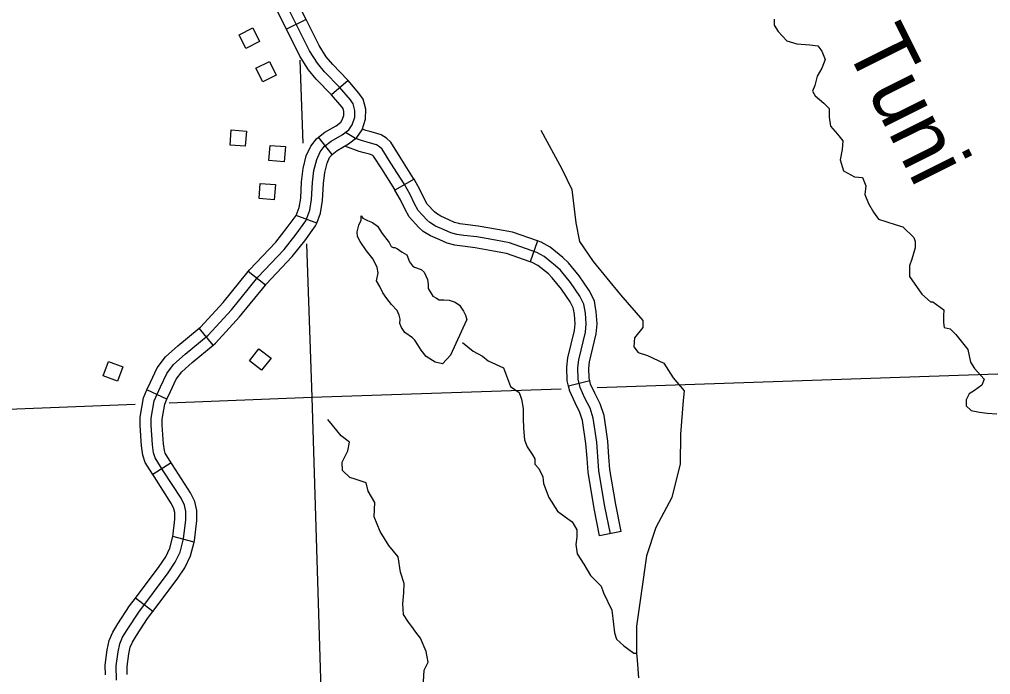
# Model space of a CAD drawing. Extents: x 155 to 3386, y 68 to 2138.
# Drawn here: x 1964.7 to 2154, y 695.1 to 823 of the extents above; entities that cross this region are included whole.
import ezdxf

# ---------------------------------------------------------------- set-up
doc = ezdxf.new("R2010")
doc.units = 0
for name, color, linetype in [('Level 32', 7, 'Continuous'), ('Level 35', 7, 'Continuous'), ('Level 45', 7, 'Continuous'), ('Level 5', 7, 'Continuous'), ('Level 56', 7, 'Continuous')]:
    doc.layers.add(name, color=color, linetype=linetype)

msp = doc.modelspace()

# ---------------------------------------------------------------- linework, layer by layer
at = {"layer": 'Level 32'}
for p, q in [((2020.58, 822.99), (2016.74, 821.09)), ((2028.74, 811.1), (2025.5, 808.3)), ((2025.62, 796.64), (2022.98, 800.02)), ((2022.63, 783.26), (2018.61, 784.73)), ((2012.62, 771.12), (2009.29, 773.82)), ((2002.44, 759.42), (1999.72, 762.73)), ((1993.44, 748.91), (1989.54, 750.69)), ((1994.27, 736.48), (1990.65, 734.19)), ((1998.74, 721.01), (1994.59, 722.09)), ((1990.7, 707.46), (1987.27, 710.04))]:
    msp.add_line(p, q, dxfattribs=at)
for points in [[(2020.58, 822.99), (2017.67, 828.87), (2016.14, 831.82), (2015, 833.02), (2013.94, 833.86), (2012.55, 834.71), (2011.19, 835.34), (2010.34, 835.57)], [(2016.74, 821.09), (2013.85, 826.93), (2012.62, 829.3), (2012.09, 829.85), (2011.48, 830.34), (2010.53, 830.92), (2009.72, 831.3), (2009.21, 831.44)], [(1983.57, 694.07), (1983.53, 696.88), (1983.91, 699.6), (1984.24, 701.14), (1984.78, 702.44), (1985.66, 703.9), (1987.92, 707.32), (1993.68, 715.01), (1995.05, 717.06), (1996.01, 719.06), (1996.68, 721.61), (1997.1, 725.33), (1997.1, 726.96), (1996.85, 728.21), (1996.18, 729.55), (1992.72, 734.93), (1991.13, 737.44), (1990.84, 738.4), (1990.63, 739.99), (1990.34, 743.79), (1990.38, 745.21), (1990.92, 748.55), (1992.17, 751.31), (1993.38, 753.9), (1994.72, 755.69), (1996.97, 757.7), (2001.44, 761.37), (2005.99, 766.34), (2011.17, 772.73), (2016.26, 778.12), (2018.6, 781.09), (2020.52, 783.72), (2021.27, 785.76), (2021.65, 787.89), (2021.81, 791.15), (2022.1, 793.51), (2022.65, 795.68), (2023.31, 797.18), (2024.11, 798.19), (2025.44, 799.23), (2027.61, 800.48), (2028.91, 801.49), (2029.58, 802.45), (2030.04, 803.91), (2030.08, 805.24), (2029.74, 806.54), (2029.2, 807.29), (2027.07, 809.76), (2024.15, 812.78), (2022.77, 814.45), (2021.23, 816.87), (2015.76, 827.9)], [(2028.74, 811.1), (2028.65, 811.2), (2025.75, 814.21), (2024.51, 815.71), (2023.1, 817.93), (2020.58, 822.99)], [(2025.5, 808.3), (2025.49, 808.31), (2022.55, 811.35), (2021.04, 813.19), (2019.36, 815.82), (2016.74, 821.09)], [(2025.62, 796.64), (2026.65, 797.45), (2028.81, 798.7), (2030.48, 799.99), (2031.52, 801.49), (2032.17, 803.55), (2032.23, 805.48), (2031.72, 807.47), (2030.88, 808.62), (2028.74, 811.1)], [(2022.98, 800.02), (2024.24, 801.01), (2026.42, 802.27), (2027.34, 802.98), (2027.63, 803.4), (2027.9, 804.27), (2027.93, 805.01), (2027.77, 805.61), (2027.52, 805.96), (2025.5, 808.3)], [(2018.61, 784.73), (2019.19, 786.32), (2019.51, 788.14), (2019.68, 791.34), (2019.99, 793.9), (2020.61, 796.38), (2021.47, 798.3), (2022.59, 799.72), (2022.98, 800.02)], [(2022.63, 783.26), (2023.35, 785.2), (2023.78, 787.65), (2023.95, 790.97), (2024.21, 793.11), (2024.68, 794.98), (2025.16, 796.07), (2025.63, 796.66), (2025.62, 796.64)], [(2009.29, 773.82), (2009.55, 774.15), (2014.64, 779.52), (2016.89, 782.38), (2018.61, 784.74), (2018.61, 784.73)], [(2012.62, 771.12), (2012.78, 771.32), (2017.88, 776.72), (2020.31, 779.79), (2022.43, 782.7), (2022.63, 783.26)], [(1999.72, 762.73), (1999.96, 762.93), (2004.37, 767.74), (2009.29, 773.82)], [(2002.44, 759.42), (2002.92, 759.81), (2007.61, 764.94), (2012.62, 771.12)], [(1989.54, 750.69), (1990.23, 752.2), (1991.53, 755), (1993.13, 757.15), (1995.58, 759.33), (1999.72, 762.73)], [(1993.44, 748.91), (1994.12, 750.41), (1995.23, 752.79), (1996.31, 754.24), (1998.37, 756.07), (2002.44, 759.42)], [(1990.65, 734.19), (1989.16, 736.54), (1988.74, 737.95), (1988.5, 739.77), (1988.19, 743.74), (1988.24, 745.41), (1988.85, 749.18), (1989.54, 750.69)], [(1994.27, 736.48), (1993.09, 738.34), (1992.94, 738.86), (1992.76, 740.21), (1992.48, 743.84), (1992.52, 745), (1992.99, 747.92), (1993.44, 748.91)], [(1998.74, 721.01), (1998.79, 721.22), (1999.24, 725.21), (1999.24, 727.17), (1998.89, 728.91), (1998.05, 730.61), (1994.52, 736.09), (1994.27, 736.48)], [(1994.57, 722), (1994.96, 725.45), (1994.96, 726.75), (1994.8, 727.51), (1994.32, 728.49), (1990.91, 733.78), (1990.65, 734.19)], [(1987.27, 710.04), (1991.93, 716.25), (1993.19, 718.12), (1993.99, 719.8), (1994.59, 722.09)], [(1990.7, 707.46), (1995.42, 713.77), (1996.92, 715.99), (1998.03, 718.32), (1998.74, 721.01)], [(1981.42, 695.08), (1981.39, 697.01), (1981.8, 699.97), (1982.19, 701.79), (1982.87, 703.41), (1983.85, 705.04), (1986.16, 708.56), (1987.27, 710.04)], [(1985.7, 695.14), (1985.68, 696.75), (1986.02, 699.22), (1986.29, 700.5), (1986.7, 701.47), (1987.48, 702.76), (1989.67, 706.09), (1990.7, 707.46)]]:
    msp.add_lwpolyline(points, dxfattribs=at)
at = {"layer": 'Level 35'}
for points in [[(2111.85, 823.07), (2111.85, 821.88), (2112.59, 820.62), (2114.3, 818.84), (2116.23, 818.25), (2118.82, 818.03), (2120.38, 817.88), (2121.12, 816.84), (2121.79, 815.21), (2121.12, 813.5), (2120.23, 811.94), (2119.79, 810.09), (2119.34, 808.98), (2119.86, 808.09), (2121.49, 806.68), (2122.53, 805.64), (2122.53, 803.93), (2122.83, 802.15), (2124.16, 800.59), (2125.2, 799.33), (2125.12, 797.63), (2124.68, 795.62), (2125.35, 793.47), (2127.5, 792.28), (2129.05, 792.14), (2129.72, 790.5), (2129.5, 788.87), (2130.24, 787.09), (2131.2, 785.38), (2132.17, 784.02), (2135.43, 782.98), (2136.91, 782.54), (2139.06, 780.46), (2139.36, 779.64), (2139.36, 778.46)], [(2066.31, 801.42), (2070.45, 793.84), (2072.37, 789.79), (2073.18, 783.33), (2073.88, 779.69), (2076.51, 775.74), (2081.86, 769.24), (2086.21, 764.28), (2086.21, 762.87), (2084.59, 760.85), (2084.49, 759.13), (2085.3, 758.02), (2087.12, 757.41), (2090.35, 755.89), (2092.17, 753.06), (2094.29, 750.54), (2094.09, 748.61), (2093.58, 742.04), (2093.48, 736.28), (2091.87, 729.71), (2088.73, 723.85), (2086.91, 718.35), (2085.9, 710.97), (2085, 704.6), (2085, 699.35), (2085.14, 697.94), (2085.4, 694.5)], [(2047.15, 755.77), (2045.73, 756.11), (2043.98, 757.23), (2043.02, 758.49), (2042.35, 759.53), (2041.77, 760.41), (2041.31, 760.87), (2039.8, 761.91), (2039.18, 762.91), (2038.84, 763.67), (2038.89, 764.54), (2038.72, 765.29), (2038.3, 766.17), (2037.22, 767.38), (2036.3, 768.55), (2035.5, 769.64), (2034.92, 770.89), (2034.29, 771.98), (2034.59, 773.52), (2034.42, 774.57), (2033.63, 776.24), (2032.33, 777.87), (2031.08, 779.66), (2030.58, 780.62), (2030.54, 781.54), (2030.87, 782.84), (2031.33, 783.83), (2031.33, 784.67), (2031.66, 784.21), (2032.54, 783.79), (2033.54, 783.37), (2034.46, 782.66), (2035.38, 781.24), (2036.76, 779.49), (2037.17, 778.7), (2037.55, 778.49), (2037.88, 778.49), (2038.38, 778.24), (2039.3, 777.57), (2040.18, 777.07), (2040.72, 775.69), (2041.31, 774.94), (2041.68, 774.69), (2043.02, 774.19), (2043.56, 773.68), (2044.23, 772.22), (2044.35, 771.26), (2044.35, 770.47), (2045.31, 769.01), (2045.98, 768.59), (2046.52, 768.3), (2047.44, 768.26), (2048.44, 768.21), (2049.66, 767.84), (2050.49, 767.21), (2051.28, 766.08), (2051.62, 765.29), (2051.91, 764.38)], [(2139.36, 778.46), (2138.69, 776.23), (2138.25, 774.9), (2138.25, 772.82), (2140.62, 769.41), (2142.33, 767.92), (2142.77, 767.92), (2144.92, 766.36), (2144.85, 765.18), (2144.85, 763.84), (2145, 762.88), (2146.18, 762.65), (2147.29, 761.54), (2149.59, 758.57), (2150.11, 756.13), (2150.93, 754.86), (2152.78, 752.83), (2152.34, 751.65), (2150.93, 750.61), (2149.89, 749.94), (2149.3, 748.75), (2149.3, 747.57), (2150.26, 746.68), (2151.89, 746.38), (2153.37, 746.16), (2155.23, 746.01)], [(2047.15, 755.77), (2048.82, 757.53), (2051.91, 764.38)], [(2051.05, 759.94), (2053.17, 758.27), (2054.99, 757.31), (2056.05, 756.4), (2059.08, 755.04), (2060.04, 752.41), (2060.44, 751.35), (2062.11, 750.18), (2062.56, 748.87), (2062.92, 747.05), (2062.92, 745.13), (2062.97, 743.21), (2063.12, 740.99), (2063.67, 739.57), (2064.68, 738.06), (2065.19, 737.25), (2065.19, 736.24), (2065.95, 735.38), (2066.7, 733.76), (2066.86, 732.45), (2067.87, 729.72), (2069.58, 727.04), (2071.1, 725.93), (2072.46, 724.97), (2072.67, 724.61), (2073.37, 723.4), (2073.37, 721.98), (2073.17, 720.52), (2073.42, 718.7), (2074.69, 716.68), (2076.05, 714.5), (2078.07, 712.38), (2078.58, 711.12), (2080.19, 707.73), (2080.5, 705), (2080.7, 703.28), (2081.1, 702.07), (2082.52, 700.77), (2084.44, 699.35), (2085, 699.35)], [(2043.39, 692.71), (2043.6, 696), (2044.4, 697.57), (2044, 699.65), (2042.89, 702.23), (2041.98, 703.39), (2041.17, 704.55), (2040.51, 705.36), (2039.55, 706.88), (2039.45, 708.95), (2039.6, 711.07), (2039.66, 712.94), (2038.95, 715.16), (2038.49, 718.15), (2036.73, 720.32), (2035.01, 723.1), (2033.85, 725.93), (2033.95, 728.73), (2032.68, 730.95), (2032.28, 732.57), (2030.11, 733.28), (2029.1, 733.63), (2027.68, 734.95), (2027.63, 736.61), (2028.69, 738.79), (2029, 740.51), (2027.38, 741.77), (2025.71, 743.84), (2024.79, 744.94)]]:
    msp.add_lwpolyline(points, dxfattribs=at)
at = {"layer": 'Level 45'}
for p, q in [((2041.63, 791.81), (2037.9, 789.7)), ((2065.67, 779.77), (2064.26, 775.73)), ((2075.89, 752.47), (2071.72, 751.46)), ((2081.99, 723.04), (2077.78, 722.22))]:
    msp.add_line(p, q, dxfattribs=at)
for points in [[(2041.63, 791.81), (2041.53, 791.98), (2038.93, 796.13), (2037.07, 799.03), (2036.24, 799.85), (2035.2, 800.47), (2034.17, 800.8), (2033.02, 801.12), (2032.21, 801.33), (2031.55, 801.58)], [(2079.89, 722.63), (2078.84, 727.95), (2077.67, 734.89), (2077.26, 740.48), (2076.57, 745.2), (2075.94, 747.15), (2074.93, 749.12), (2074, 751.15), (2073.61, 752.77), (2073.55, 755.07), (2073.73, 756.56), (2075.02, 761.97), (2075.16, 763.59), (2075.02, 765.68), (2074.72, 767.42), (2073.91, 769), (2072.09, 771.66), (2070.14, 774.05), (2069.22, 774.95), (2066.98, 776.74), (2065.54, 777.55), (2060.22, 779.4), (2057.5, 779.91), (2053.83, 780.57), (2051.35, 780.87), (2049.97, 781.05), (2048.78, 781.35), (2047.52, 781.95), (2045.82, 782.69), (2044.68, 783.38), (2044.09, 783.92), (2042.41, 785.71), (2041.73, 787), (2040.86, 788.82), (2039.69, 790.89), (2037.12, 794.98), (2035.39, 797.67), (2034.91, 798.15), (2034.31, 798.51), (2033.57, 798.75), (2032.46, 799.05), (2031.57, 799.29), (2030.19, 799.8), (2029.2, 800.36), (2028.58, 800.75), (2028.24, 800.97)], [(2037.9, 789.7), (2037.85, 789.79), (2035.32, 793.83), (2033.71, 796.32), (2033.58, 796.45), (2033.42, 796.54), (2032.96, 796.69), (2031.91, 796.98), (2030.92, 797.24), (2028.09, 798.29)], [(2050.57, 783.13), (2050.37, 783.16), (2049.51, 783.38), (2048.41, 783.9), (2046.81, 784.6), (2045.97, 785.11), (2045.59, 785.45), (2044.17, 786.97), (2043.64, 787.96), (2042.76, 789.81), (2041.63, 791.81)], [(2050.02, 778.88), (2049.57, 778.94), (2048.05, 779.32), (2046.63, 780), (2044.83, 780.79), (2043.4, 781.65), (2042.58, 782.39), (2040.66, 784.46), (2039.81, 786.03), (2038.96, 787.83), (2037.9, 789.7)], [(2065.67, 779.77), (2060.78, 781.48), (2057.89, 782.02), (2054.15, 782.69), (2051.61, 783), (2050.57, 783.13)], [(2064.26, 775.73), (2059.67, 777.33), (2057.12, 777.81), (2053.51, 778.45), (2051.08, 778.74), (2050.02, 778.88)], [(2076.93, 767.2), (2076.77, 768.1), (2075.76, 770.1), (2073.81, 772.94), (2071.73, 775.5), (2070.64, 776.56), (2068.18, 778.53), (2066.43, 779.51), (2065.67, 779.77)], [(2072.7, 766.47), (2072.66, 766.73), (2072.06, 767.9), (2070.37, 770.38), (2068.56, 772.6), (2067.8, 773.34), (2065.77, 774.96), (2064.66, 775.59), (2064.26, 775.73)], [(2075.89, 752.47), (2075.75, 753.05), (2075.7, 754.97), (2075.84, 756.19), (2077.13, 761.63), (2077.31, 763.57), (2077.15, 765.94), (2076.93, 767.2)], [(2071.72, 751.46), (2071.47, 752.48), (2071.4, 755.17), (2071.62, 756.94), (2072.9, 762.32), (2073.01, 763.61), (2072.89, 765.42), (2072.7, 766.47)], [(2079.62, 737.67), (2079.39, 740.71), (2078.66, 745.69), (2077.93, 747.97), (2076.85, 750.05), (2076.03, 751.85), (2075.89, 752.47)], [(2075.34, 737.35), (2075.13, 740.24), (2074.47, 744.71), (2073.96, 746.32), (2073, 748.18), (2071.96, 750.45), (2071.72, 751.46)], [(2077.78, 722.22), (2076.73, 727.57), (2075.55, 734.63), (2075.34, 737.35)], [(2081.99, 723.04), (2080.95, 728.33), (2079.8, 735.14), (2079.62, 737.67)]]:
    msp.add_lwpolyline(points, dxfattribs=at)
at = {"layer": 'Level 5'}
for points in [[(2019.33, 815.06), (2019.92, 798.87)], [(2020.63, 779.21), (2021.71, 749.3)], [(2077.31, 751.18), (2170.66, 754.35)], [(2021.71, 749.3), (2070.31, 750.94)], [(1993.85, 748.19), (2021.71, 749.3)], [(2021.71, 749.3), (2026.33, 599.15)], [(1873.38, 743.4), (1987.21, 747.92)]]:
    msp.add_lwpolyline(points, dxfattribs=at)
at = {"layer": 'Level 56'}
for points in [[(2011.49, 818.68), (2008.83, 817.36), (2007.5, 820.03), (2010.17, 821.35)], [(2014.76, 812.12), (2012.1, 810.8), (2010.77, 813.47), (2013.43, 814.79)], [(2008.7, 798.25), (2005.74, 798.49), (2005.98, 801.46), (2008.94, 801.23)], [(2016.29, 795.21), (2013.33, 795.45), (2013.56, 798.42), (2016.53, 798.18)], [(2014.36, 787.79), (2011.39, 788.03), (2011.63, 791), (2014.59, 790.76)], [(2009.55, 756.4), (2011.38, 758.74), (2013.73, 756.9), (2011.89, 754.56)], [(1984.82, 755.19), (1983.76, 752.41), (1980.97, 753.47), (1982.04, 756.25)]]:
    msp.add_lwpolyline(points, close=True, dxfattribs=at)

# ---------------------------------------------------------------- texts
at = {"layer": 'Level 35'}
msp.add_text('Tuni', height=12.069, rotation=296.5519, dxfattribs=at).set_placement((2125.52, 817.93))

doc.saveas('drawing.dxf')
